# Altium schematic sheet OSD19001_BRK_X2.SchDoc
size B; Organization: Altium Limited; DocumentNumber: 1; SheetNumber: 1; SheetTotal: 4; SchematicTitle: OSD32MP1 BREAKOUT MODULE
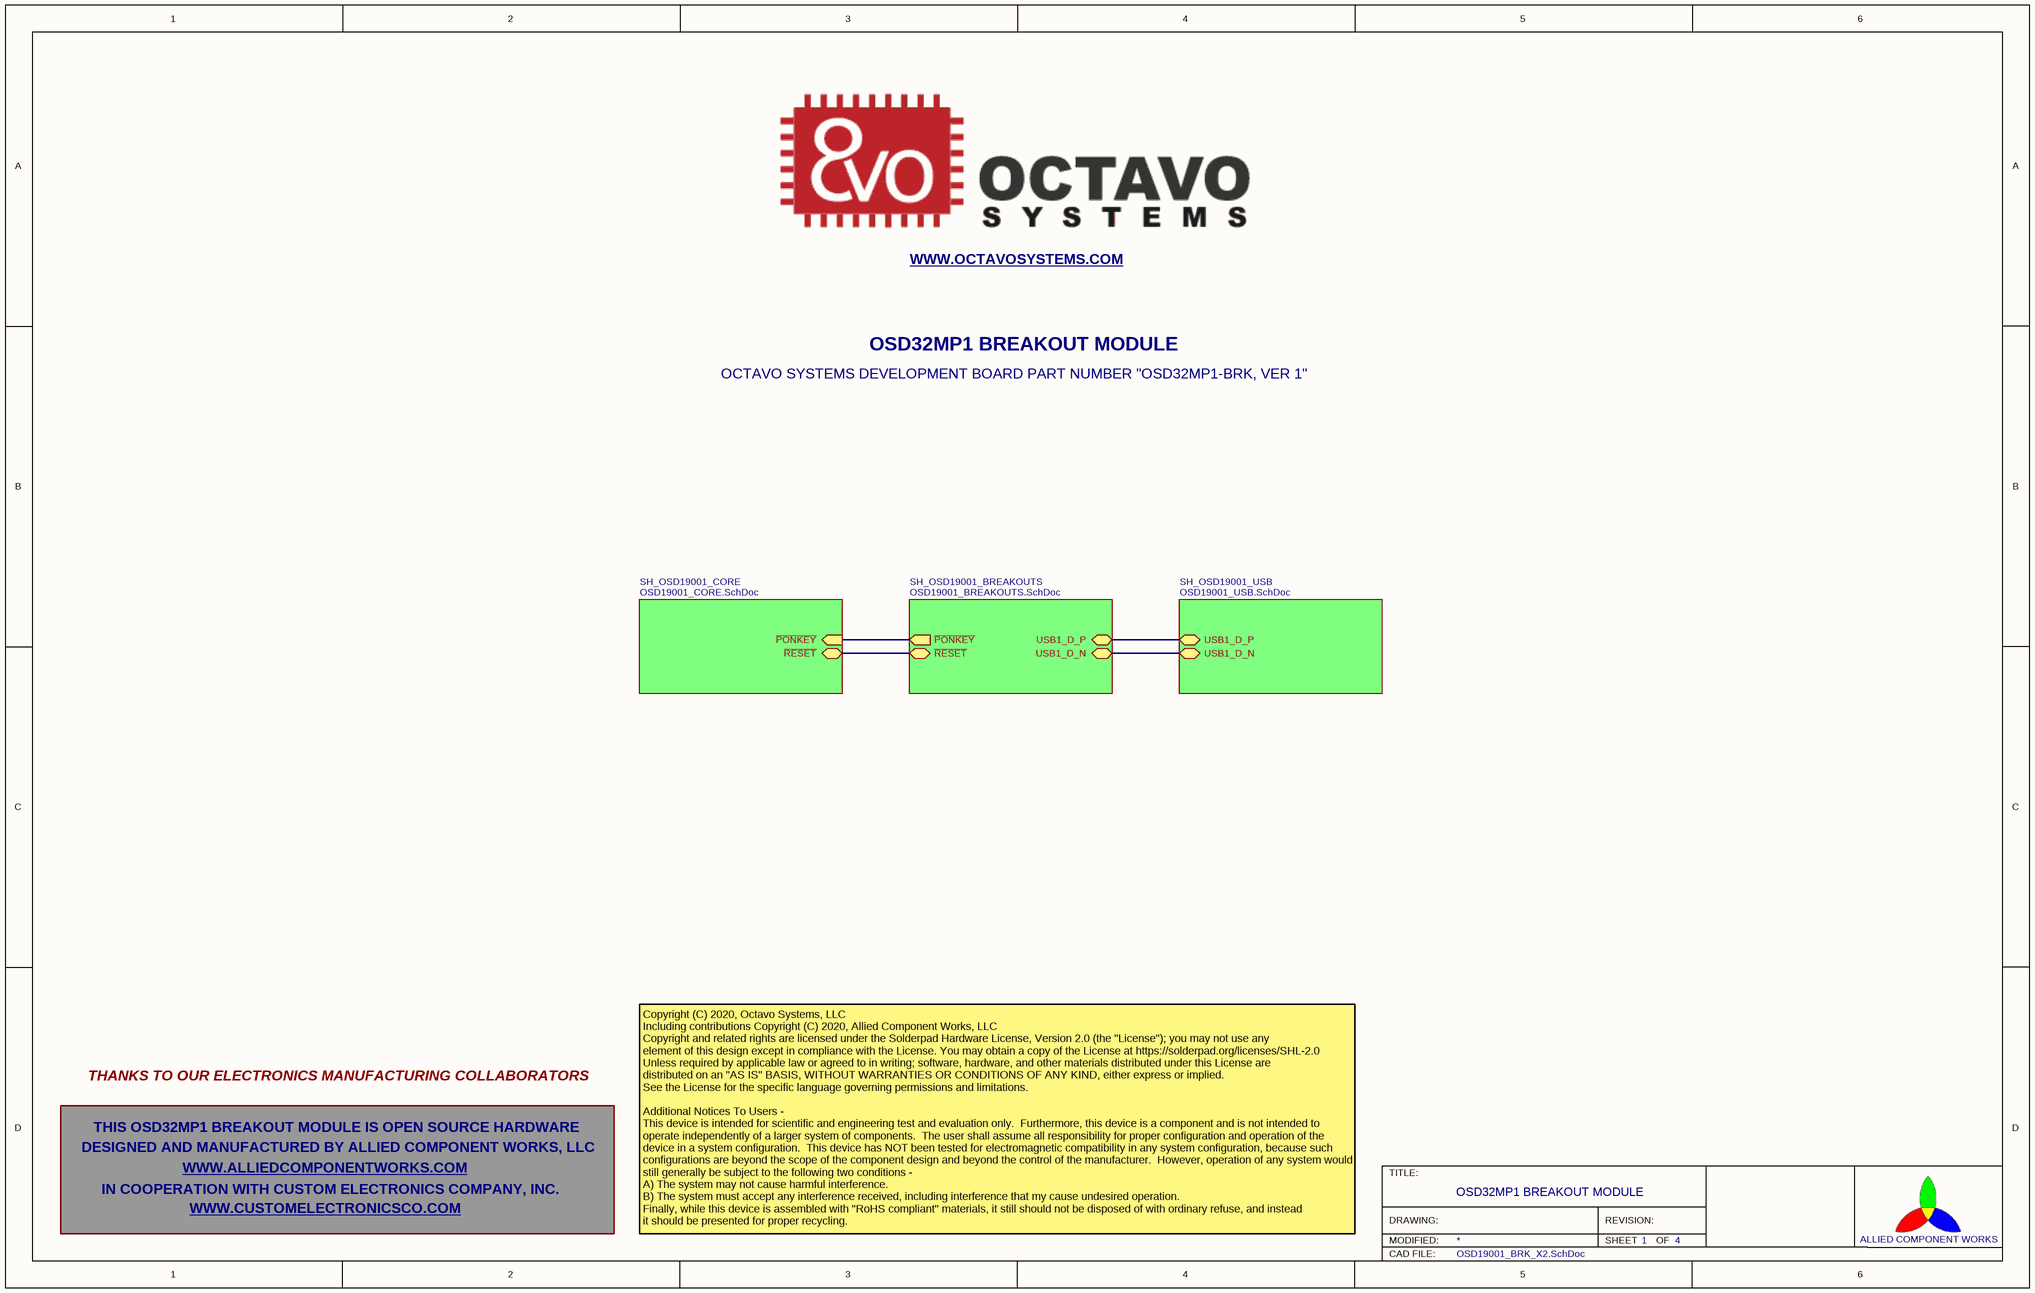
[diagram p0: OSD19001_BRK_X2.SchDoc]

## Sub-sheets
SH_OSD19001_BREAKOUTS = OSD19001_BREAKOUTS.SchDoc: ~{PONKEY} (out), ~{RESET} (bidir), USB1_D_P (bidir), USB1_D_N (bidir)
SH_OSD19001_CORE = OSD19001_CORE.SchDoc: ~{PONKEY} (in), ~{RESET} (bidir)
SH_OSD19001_USB = OSD19001_USB.SchDoc: USB1_D_P (bidir), USB1_D_N (bidir)

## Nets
(unnamed): sheet SH_OSD19001_CORE/~{PONKEY}, sheet SH_OSD19001_BREAKOUTS/~{PONKEY}
(unnamed): sheet SH_OSD19001_CORE/~{RESET}, sheet SH_OSD19001_BREAKOUTS/~{RESET}  [a separate net that carries the same name]
(unnamed): sheet SH_OSD19001_BREAKOUTS/USB1_D_P, sheet SH_OSD19001_USB/USB1_D_P  [a separate net that carries the same name]
(unnamed): sheet SH_OSD19001_BREAKOUTS/USB1_D_N, sheet SH_OSD19001_USB/USB1_D_N  [a separate net that carries the same name]

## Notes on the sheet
- WWW.OCTAVOSYSTEMS.COM <http://WWW.OCTAVOSYSTEMS.COM>
- OSD32MP1 BREAKOUT MODULE
- OCTAVO SYSTEMS DEVELOPMENT BOARD PART NUMBER "OSD32MP1-BRK, VER 1"
- THANKS TO OUR ELECTRONICS MANUFACTURING COLLABORATORS
- DESIGNED AND MANUFACTURED BY ALLIED COMPONENT WORKS, LLC
- THIS OSD32MP1 BREAKOUT MODULE IS OPEN SOURCE HARDWARE
- WWW.ALLIEDCOMPONENTWORKS.COM <http://WWW.ALLIEDCOMPONENTWORKS.COM>
- IN COOPERATION WITH CUSTOM ELECTRONICS COMPANY, INC.
- WWW.CUSTOMELECTRONICSCO.COM <http://WWW.CUSTOMELECTRONICSCO.COM>
- Copyright (C) 2020, Octavo Systems, LLC
  Including contributions Copyright (C) 2020, Allied Component Works, LLC
  Copyright and related rights are licensed under the Solderpad Hardware License, Version 2.0 (the "License"); you may not use any
  element of this design except in compliance with the License. You may obtain a copy of the License at https://solderpad.org/licenses/SHL-2.0
  Unless required by applicable law or agreed to in writing; software, hardware, and other materials distributed under this License are
  distributed on an "AS IS" BASIS, WITHOUT WARRANTIES OR CONDITIONS OF ANY KIND, either express or implied.
  See the License for the specific language governing permissions and limitations.
  Additional Notices To Users -
  This device is intended for scientific and engineering test and evaluation only.  Furthermore, this device is a component and is not intended to operate independently of a larger system of components.  The user shall assume all responsibility for proper configuration and operation of the device in a system configuration.  This device has NOT been tested for electromagnetic compatibility in any system configuration, because such configurations are beyond the scope of the component design and beyond the control of the manufacturer.  However, operation of any system would still generally be subject to the following two conditions -
  A) The system may not cause harmful interference.
  B) The system must accept any interference received, including interference that my cause undesired operation.
  Finally, while this device is assembled with "RoHS compliant" materials, it still should not be disposed of with ordinary refuse, and instead
  it should be presented for proper recycling.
